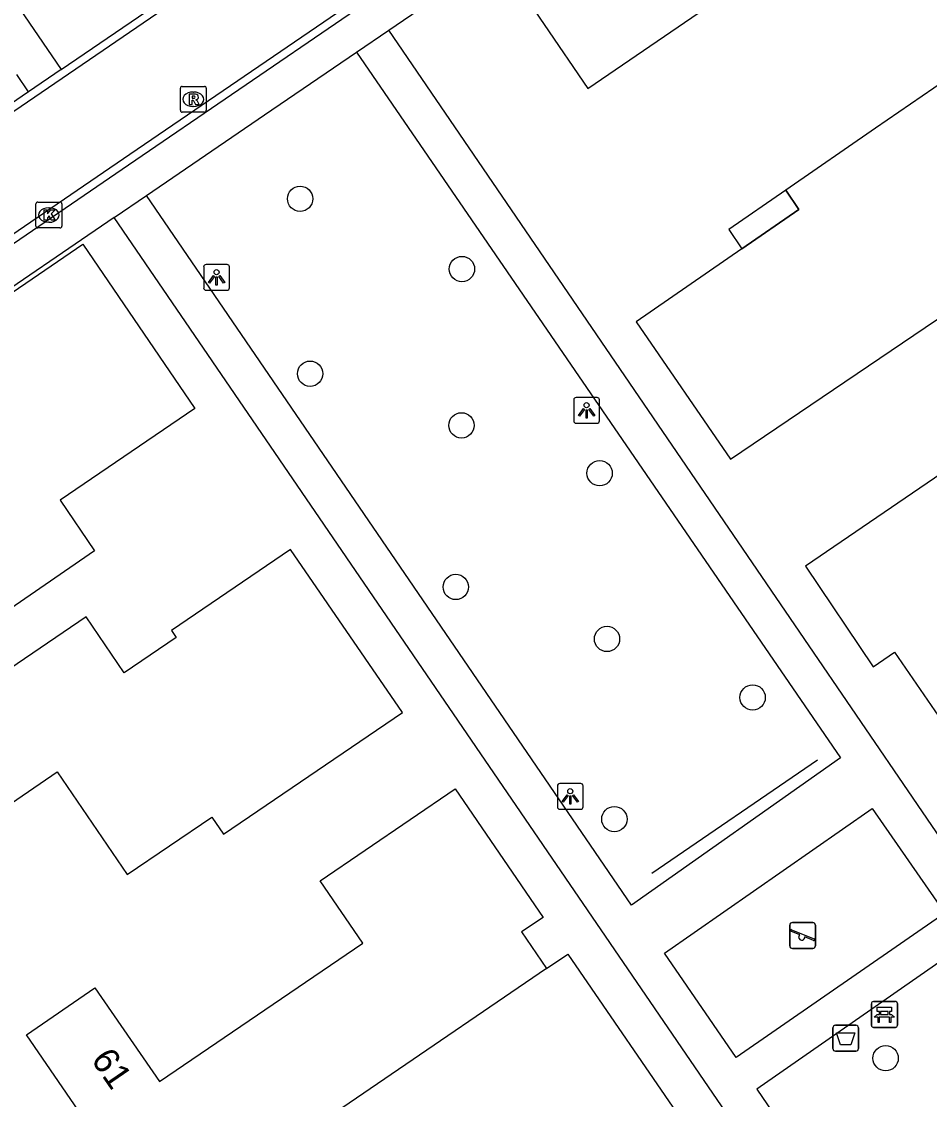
# Model space of a CAD drawing. Extents: x 155275 to 156263, y 382654 to 383635.
# Drawn here: x 155711.19 to 155746.27, y 383313.6 to 383355.27 of the extents above; entities that cross this region are included whole.
import ezdxf

# ---------------------------------------------------------------- set-up
doc = ezdxf.new("R2010")
doc.units = 0
for name, color, linetype in [('IMGEO_Afvalbak', 7, 'Continuous'), ('IMGEO_Bank', 7, 'Continuous'), ('IMGEO_Boom', 7, 'Continuous'), ('IMGEO_Hek', 7, 'Continuous'), ('IMGEO_Kolk', 7, 'Continuous'), ('IMGEO_Lichtpunt', 7, 'Continuous'), ('IMGEO_Pand', 7, 'Continuous'), ('IMGEO_Pand_nummerreeks', 7, 'Continuous'), ('IMGEO_Pand_overbouw', 7, 'Continuous'), ('IMGEO_Rijbaan_lokaal_gesloten', 7, 'Continuous'), ('IMGEO_Rioolput', 7, 'Continuous'), ('IMGEO_Speelvoorziening', 7, 'Continuous'), ('IMGEO_Voetpad_open', 7, 'Continuous')]:
    doc.layers.add(name, color=color, linetype=linetype)

msp = doc.modelspace()

# ---------------------------------------------------------------- linework, layer by layer
at = {"layer": 'IMGEO_Afvalbak'}
for p, q in [((155742.535, 383315.568), (155742.535, 383316.368)), ((155742.535, 383316.368), (155742.535, 383315.568)), ((155742.635, 383316.468), (155743.425, 383316.468)), ((155743.425, 383316.468), (155742.635, 383316.468)), ((155743.525, 383316.368), (155743.525, 383315.568)), ((155743.525, 383315.568), (155743.525, 383316.368)), ((155743.425, 383315.468), (155742.635, 383315.468)), ((155742.635, 383315.468), (155743.425, 383315.468))]:
    msp.add_line(p, q, dxfattribs=at)
msp.add_lwpolyline([(155742.678, 383316.182), (155743.382, 383316.182), (155743.233, 383315.712), (155742.827, 383315.712), (155742.678, 383316.182)], dxfattribs=at)
for centre, start, end in [((155742.635, 383316.368), 90, 180), ((155742.635, 383316.368), 90, 180), ((155743.425, 383316.368), 0, 90), ((155743.425, 383316.368), 360, 90), ((155742.635, 383315.568), 180, 270), ((155742.635, 383315.568), 180, 270), ((155743.425, 383315.568), 270, 0), ((155743.425, 383315.568), 270, 0)]:
    msp.add_arc(centre, 0.1, start, end, dxfattribs=at)
at = {"layer": 'IMGEO_Bank'}
for p, q in [((155744.028, 383316.463), (155744.028, 383317.304)), ((155744.028, 383317.304), (155744.028, 383316.463)), ((155744.103, 383317.388), (155744.944, 383317.388)), ((155744.944, 383317.388), (155744.103, 383317.388)), ((155744.337, 383316.894), (155744.337, 383317)), ((155744.381, 383317), (155744.381, 383316.894)), ((155744.669, 383317.006), (155744.387, 383317.006)), ((155744.675, 383316.894), (155744.675, 383317)), ((155744.719, 383317), (155744.719, 383316.894)), ((155745.028, 383317.313), (155745.028, 383316.472)), ((155745.028, 383316.472), (155745.028, 383317.313)), ((155744.725, 383316.786), (155744.332, 383316.786)), ((155744.387, 383316.888), (155744.669, 383316.888)), ((155744.953, 383316.388), (155744.112, 383316.388)), ((155744.112, 383316.388), (155744.953, 383316.388))]:
    msp.add_line(p, q, dxfattribs=at)
for points in [[(155744.331, 383317.006), (155744.245, 383317.006), (155744.245, 383317.167), (155744.808, 383317.167), (155744.808, 383317.006), (155744.725, 383317.006)], [(155744.275, 383316.786), (155744.133, 383316.786), (155744.245, 383316.888), (155744.331, 383316.888)], [(155744.325, 383316.779), (155744.325, 383316.572), (155744.282, 383316.572), (155744.282, 383316.779)], [(155744.725, 383316.888), (155744.808, 383316.888), (155744.92, 383316.786), (155744.781, 383316.786)], [(155744.775, 383316.779), (155744.775, 383316.572), (155744.731, 383316.572), (155744.731, 383316.779)]]:
    msp.add_lwpolyline(points, dxfattribs=at)
for centre, radius, start, end in [((155744.106, 383317.31), 0.0779, 92.4484, 184.2845), ((155744.106, 383317.31), 0.0779, 92.4484, 184.2845), ((155744.33, 383316.999), 0.00671, 2.8957, 87.1043), ((155744.387, 383316.999), 0.00671, 92.8957, 177.1043), ((155744.669, 383316.999), 0.00671, 2.8957, 87.1043), ((155744.726, 383316.999), 0.00671, 92.8957, 177.1043), ((155744.95, 383317.31), 0.0779, 2.4484, 94.2845), ((155744.95, 383317.31), 0.0779, 2.4484, 94.2845), ((155744.275, 383316.779), 0.00671, 2.8957, 87.1043), ((155744.332, 383316.779), 0.00671, 92.8957, 177.1043), ((155744.33, 383316.895), 0.00671, 272.8957, 357.1043), ((155744.387, 383316.895), 0.00671, 182.8957, 267.1043), ((155744.669, 383316.895), 0.00671, 272.8957, 357.1043), ((155744.726, 383316.895), 0.00671, 182.8957, 267.1043), ((155744.724, 383316.779), 0.00671, 2.8957, 87.1043), ((155744.781, 383316.779), 0.00671, 92.8957, 177.1043), ((155744.106, 383316.466), 0.0779, 182.4484, 274.2845), ((155744.106, 383316.466), 0.0779, 182.4484, 274.2845), ((155744.95, 383316.466), 0.0779, 272.4484, 4.2845), ((155744.95, 383316.466), 0.0779, 272.4484, 4.2845)]:
    msp.add_arc(centre, radius, start, end, dxfattribs=at)
at = {"layer": 'IMGEO_Boom'}
for centre in [(155721.954, 383348.418), (155728.207, 383345.703), (155722.34, 383341.656), (155728.188, 383339.659), (155733.527, 383337.809), (155727.968, 383333.413), (155733.811, 383331.402), (155739.437, 383329.141), (155734.096, 383324.438), (155744.576, 383315.195)]:
    msp.add_circle(centre, 0.489, dxfattribs=at)
at = {"layer": 'IMGEO_Hek'}
msp.add_lwpolyline([(155735.54, 383322.354), (155741.949, 383326.733)], dxfattribs=at)
at = {"layer": 'IMGEO_Kolk'}
for p, q in [((155711.824, 383348.291), (155712.676, 383348.291)), ((155711.749, 383347.365), (155711.749, 383348.217)), ((155712.237, 383348.071), (155712.262, 383348.071)), ((155712.75, 383348.217), (155712.75, 383347.365)), ((155712.26, 383347.511), (155712.235, 383347.511)), ((155712.676, 383347.291), (155711.824, 383347.291))]:
    msp.add_line(p, q, dxfattribs=at)
for points in [[(155711.824, 383348.291), (155712.676, 383348.291)], [(155711.749, 383347.365), (155711.749, 383348.217)], [(155712.07, 383347.991), (155712.193, 383347.991), (155712.193, 383347.84), (155712.323, 383347.991), (155712.487, 383347.991), (155712.341, 383347.84), (155712.494, 383347.591), (155712.342, 383347.591), (155712.257, 383347.755), (155712.193, 383347.688), (155712.193, 383347.591), (155712.07, 383347.591), (155712.07, 383347.991)], [(155712.75, 383348.217), (155712.75, 383347.365)], [(155712.676, 383347.291), (155711.824, 383347.291)]]:
    msp.add_lwpolyline(points, dxfattribs=at)
for centre, start, end in [((155711.826, 383348.215), 91.552, 178.448), ((155711.826, 383348.215), 91.552, 178.448), ((155712.674, 383348.215), 1.552, 88.448), ((155712.674, 383348.215), 1.552, 88.448), ((155711.826, 383347.367), 181.552, 268.448), ((155711.826, 383347.367), 181.552, 268.448), ((155712.674, 383347.367), 271.552, 358.448), ((155712.674, 383347.367), 271.552, 358.448)]:
    msp.add_arc(centre, 0.0765, start, end, dxfattribs=at)
for centre, major_axis, ratio, start_param, end_param in [((155712.236, 383347.791), (-0.387, 0.002), 0.722429, 4.712389, 7.853982), ((155712.261, 383347.791), (-0.39, 0.002), 0.717154, 1.570796, 4.712389)]:
    msp.add_ellipse(centre, major_axis=major_axis, ratio=ratio, start_param=start_param, end_param=end_param, dxfattribs=at)
at = {"layer": 'IMGEO_Lichtpunt'}
for p, q in [((155718.229, 383345.783), (155718.229, 383344.976)), ((155718.229, 383345.783), (155718.229, 383344.976)), ((155719.131, 383345.878), (155718.323, 383345.878)), ((155719.131, 383345.878), (155718.323, 383345.878)), ((155719.225, 383344.976), (155719.225, 383345.783)), ((155719.225, 383344.976), (155719.225, 383345.783)), ((155718.323, 383344.882), (155719.131, 383344.882)), ((155718.323, 383344.882), (155719.131, 383344.882)), ((155732.524, 383340.642), (155732.524, 383339.835)), ((155732.524, 383340.642), (155732.524, 383339.835)), ((155733.426, 383340.737), (155732.618, 383340.737)), ((155733.426, 383340.737), (155732.618, 383340.737)), ((155733.52, 383339.835), (155733.52, 383340.642)), ((155733.52, 383339.835), (155733.52, 383340.642)), ((155732.618, 383339.741), (155733.426, 383339.741)), ((155732.618, 383339.741), (155733.426, 383339.741)), ((155732.795, 383325.814), (155731.987, 383325.814)), ((155732.795, 383325.814), (155731.987, 383325.814)), ((155731.893, 383325.719), (155731.893, 383324.912)), ((155731.893, 383325.719), (155731.893, 383324.912)), ((155732.889, 383324.912), (155732.889, 383325.719)), ((155732.889, 383324.912), (155732.889, 383325.719)), ((155731.987, 383324.818), (155732.795, 383324.818)), ((155731.987, 383324.818), (155732.795, 383324.818))]:
    msp.add_line(p, q, dxfattribs=at)
for points in [[(155718.603, 383345.447), (155718.642, 383345.419), (155718.454, 383345.157), (155718.416, 383345.184), (155718.603, 383345.447)], [(155718.705, 383345.399), (155718.752, 383345.399), (155718.752, 383345.077), (155718.705, 383345.077), (155718.705, 383345.399)], [(155718.815, 383345.419), (155718.853, 383345.446), (155719.04, 383345.184), (155719.001, 383345.156), (155718.815, 383345.419)], [(155732.898, 383340.306), (155732.937, 383340.278), (155732.749, 383340.016), (155732.711, 383340.043), (155732.898, 383340.306)], [(155733, 383340.258), (155733.047, 383340.258), (155733.047, 383339.936), (155733, 383339.936), (155733, 383340.258)], [(155733.11, 383340.278), (155733.148, 383340.305), (155733.335, 383340.043), (155733.296, 383340.015), (155733.11, 383340.278)], [(155732.267, 383325.383), (155732.306, 383325.355), (155732.118, 383325.093), (155732.08, 383325.12), (155732.267, 383325.383)], [(155732.369, 383325.335), (155732.416, 383325.335), (155732.416, 383325.013), (155732.369, 383325.013), (155732.369, 383325.335)], [(155732.479, 383325.355), (155732.517, 383325.382), (155732.704, 383325.12), (155732.665, 383325.092), (155732.479, 383325.355)]]:
    msp.add_lwpolyline(points, dxfattribs=at)
for centre in [(155718.728, 383345.581), (155733.023, 383340.44), (155732.392, 383325.517)]:
    msp.add_circle(centre, 0.0994, dxfattribs=at)
for centre, start, end in [((155718.323, 383345.783), 90, 180), ((155718.323, 383345.783), 90, 180), ((155719.131, 383345.783), 0, 90), ((155719.131, 383345.783), 0, 90), ((155718.323, 383344.976), 180, 270), ((155718.323, 383344.976), 180, 270), ((155719.131, 383344.976), 270, 0), ((155719.131, 383344.976), 270, 360), ((155732.618, 383340.642), 90, 180), ((155732.618, 383340.642), 90, 180), ((155733.426, 383340.642), 0, 90), ((155733.426, 383340.642), 0, 90), ((155732.618, 383339.835), 180, 270), ((155732.618, 383339.835), 180, 270), ((155733.426, 383339.835), 270, 0), ((155733.426, 383339.835), 270, 360), ((155731.987, 383325.719), 90, 180), ((155731.987, 383325.719), 90, 180), ((155732.795, 383325.719), 0, 90), ((155732.795, 383325.719), 0, 90), ((155731.987, 383324.912), 180, 270), ((155731.987, 383324.912), 180, 270), ((155732.795, 383324.912), 270, 0), ((155732.795, 383324.912), 270, 360)]:
    msp.add_arc(centre, 0.0946, start, end, dxfattribs=at)
at = {"layer": 'IMGEO_Pand'}
for points in [[(155745.43, 383361.131), (155742.039, 383366.086), (155729.692, 383357.646), (155733.064, 383352.687), (155742.448, 383359.095)], [(155734.932, 383343.667), (155738.587, 383338.351), (155747.887, 383344.659), (155746.82, 383346.257), (155749.459, 383348.086), (155753.145, 383350.641), (155750.037, 383355.171), (155744.186, 383351.143), (155740.721, 383348.752), (155741.22, 383348.005), (155739.017, 383346.48), (155734.932, 383343.667)], [(155712.69, 383336.769), (155714.016, 383334.808), (155709.604, 383331.778), (155703.922, 383340.076), (155713.558, 383346.665), (155717.883, 383340.315), (155712.69, 383336.769)], [(155757.25, 383336.754), (155756.222, 383338.246), (155752.849, 383335.923), (155750.035, 383340.052), (155741.483, 383334.214), (155744.094, 383330.327), (155744.921, 383330.894), (155748.035, 383326.353), (155748.208, 383326.472)], [(155725.912, 383328.554), (155721.583, 383334.859), (155716.984, 383331.725), (155717.164, 383331.46), (155715.163, 383330.089), (155713.691, 383332.255), (155705.396, 383326.616), (155703.742, 383325.492), (155705.288, 383323.217), (155706.97, 383324.31), (155707.84, 383323.036), (155712.565, 383326.27), (155715.271, 383322.292), (155718.544, 383324.516), (155718.994, 383323.854), (155725.912, 383328.554)], [(155718.414, 383309.742), (155717.048, 383311.729), (155715.234, 383310.476), (155711.378, 383316.095), (155714.029, 383317.915), (155716.516, 383314.29), (155724.373, 383319.645), (155722.728, 383322.057), (155727.941, 383325.612), (155731.339, 383320.63), (155730.513, 383320.077), (155731.476, 383318.658)], [(155731.476, 383318.658), (155732.298, 383319.22), (155736.952, 383312.438), (155732.083, 383309.164), (155730.299, 383311.75), (155722.139, 383306.171)], [(155731.476, 383318.658), (155718.414, 383309.742)]]:
    msp.add_lwpolyline(points, dxfattribs=at)
at = {"layer": 'IMGEO_Pand_overbouw'}
msp.add_lwpolyline([(155740.721, 383348.752), (155738.519, 383347.232), (155739.017, 383346.48), (155741.22, 383348.005)], close=True, dxfattribs=at)
at = {"layer": 'IMGEO_Rijbaan_lokaal_gesloten'}
for points in [[(155779.897, 383398.895), (155721.169, 383358.828), (155661.404, 383317.986), (155661.244, 383318.235)], [(155782.106, 383395.69), (155715.377, 383350.126), (155663.845, 383314.887), (155664.009, 383314.637)], [(155693.872, 383335.059), (155715.33, 383349.733), (155745.158, 383370.123)], [(155712.721, 383353.417), (155720.795, 383358.936)], [(155712.721, 383353.417), (155711.461, 383352.556)], [(155711.461, 383352.556), (155708.502, 383350.534)]]:
    msp.add_lwpolyline(points, dxfattribs=at)
at = {"layer": 'IMGEO_Rioolput'}
for p, q in [((155717.329, 383351.838), (155717.329, 383352.69)), ((155717.404, 383352.764), (155718.256, 383352.764)), ((155717.817, 383352.544), (155717.842, 383352.544)), ((155718.33, 383352.69), (155718.33, 383351.838)), ((155718.256, 383351.764), (155717.404, 383351.764)), ((155717.84, 383351.984), (155717.815, 383351.984))]:
    msp.add_line(p, q, dxfattribs=at)
for points in [[(155717.329, 383351.838), (155717.329, 383352.69)], [(155717.404, 383352.764), (155718.256, 383352.764)], [(155717.918, 383352.462), (155717.666, 383352.464), (155717.666, 383352.064)], [(155718.33, 383352.69), (155718.33, 383351.838)], [(155717.666, 383352.064), (155717.79, 383352.064), (155717.79, 383352.226), (155717.801, 383352.226)], [(155717.844, 383352.383), (155717.79, 383352.383), (155717.79, 383352.302)], [(155717.79, 383352.302), (155717.842, 383352.302)], [(155717.848, 383352.197), (155717.919, 383352.064), (155718.059, 383352.064), (155717.994, 383352.19)], [(155718.256, 383351.764), (155717.404, 383351.764)]]:
    msp.add_lwpolyline(points, dxfattribs=at)
for centre, radius, start, end in [((155717.406, 383352.688), 0.0765, 91.552, 178.448), ((155717.406, 383352.688), 0.0765, 91.552, 178.448), ((155717.917, 383352.352), 0.109, 350.3612, 89.416), ((155718.254, 383352.688), 0.0765, 1.552, 88.448), ((155718.254, 383352.688), 0.0765, 1.552, 88.448), ((155717.8, 383352.173), 0.0533, 26.0293, 88.6989), ((155717.826, 383352.491), 0.19, 274.7715, 282.9687), ((155717.85, 383352.287), 0.0964, 77.0061, 93.1865), ((155717.864, 383352.344), 0.0378, 276.6634, 79.6772), ((155717.915, 383352.352), 0.112, 277.5842, 350.9817), ((155717.899, 383352.137), 0.108, 29.5134, 73.7905), ((155717.406, 383351.84), 0.0765, 181.552, 268.448), ((155717.406, 383351.84), 0.0765, 181.552, 268.448), ((155718.254, 383351.84), 0.0765, 271.552, 358.448), ((155718.254, 383351.84), 0.0765, 271.552, 358.448)]:
    msp.add_arc(centre, radius, start, end, dxfattribs=at)
for centre, major_axis, ratio, start_param, end_param in [((155717.816, 383352.264), (-0.387, 0.002), 0.722429, 4.712389, 7.853982), ((155717.841, 383352.264), (-0.39, 0.002), 0.717154, 1.570796, 4.712389)]:
    msp.add_ellipse(centre, major_axis=major_axis, ratio=ratio, start_param=start_param, end_param=end_param, dxfattribs=at)
at = {"layer": 'IMGEO_Speelvoorziening'}
for p, q in [((155740.872, 383319.54), (155740.872, 383320.34)), ((155740.872, 383320.34), (155740.872, 383319.54)), ((155740.972, 383320.44), (155741.762, 383320.44)), ((155741.762, 383320.44), (155740.972, 383320.44)), ((155741.862, 383320.34), (155741.862, 383319.54)), ((155741.862, 383319.54), (155741.862, 383320.34)), ((155741.255, 383319.968), (155740.916, 383320.105)), ((155740.941, 383320.165), (155741.817, 383319.812)), ((155741.793, 383319.752), (155741.453, 383319.889)), ((155741.762, 383319.44), (155740.972, 383319.44)), ((155740.972, 383319.44), (155741.762, 383319.44))]:
    msp.add_line(p, q, dxfattribs=at)
for centre, radius, start, end in [((155740.972, 383320.34), 0.1, 90, 180), ((155740.972, 383320.34), 0.1, 90, 180), ((155741.762, 383320.34), 0.1, 0, 90), ((155741.762, 383320.34), 0.1, 360, 90), ((155740.929, 383320.135), 0.0327, 68.078, 248.078), ((155741.334, 383319.878), 0.12, 130.9928, 5.1632), ((155740.972, 383319.54), 0.1, 180, 270), ((155740.972, 383319.54), 0.1, 180, 270), ((155741.762, 383319.54), 0.1, 270, 0), ((155741.762, 383319.54), 0.1, 270, 0), ((155741.805, 383319.782), 0.0327, 248.078, 68.078)]:
    msp.add_arc(centre, radius, start, end, dxfattribs=at)
at = {"layer": 'IMGEO_Voetpad_open'}
for points in [[(155725.382, 383354.939), (155745.715, 383368.811)], [(155720.795, 383358.936), (155717.961, 383363.071), (155709.882, 383357.573), (155712.721, 383353.417)], [(155724.137, 383354.089), (155725.382, 383354.939)], [(155764.327, 383297.885), (155763.878, 383298.522), (155725.382, 383354.939)], [(155716.015, 383348.542), (155720.581, 383351.663), (155724.137, 383354.089)], [(155724.137, 383354.089), (155742.832, 383326.803), (155734.762, 383321.106), (155716.015, 383348.542)], [(155711.461, 383352.556), (155711.009, 383353.222)], [(155714.768, 383347.689), (155716.015, 383348.542)], [(155714.768, 383347.689), (155698.263, 383336.406), (155694.36, 383333.757)], [(155756.341, 383286.918), (155755.683, 383287.816), (155714.768, 383347.689)], [(155744.055, 383324.846), (155746.857, 383320.807), (155738.798, 383315.226), (155736.031, 383319.256), (155744.055, 383324.846)], [(155763.51, 383296.526), (155763.357, 383296.696), (155747.691, 383319.636), (155739.6, 383314.001), (155757.081, 383288.349), (155757.279, 383288.068)]]:
    msp.add_lwpolyline(points, dxfattribs=at)

# ---------------------------------------------------------------- texts
at = {"layer": 'IMGEO_Pand_nummerreeks'}
msp.add_text('61', height=1, rotation=304.4575, dxfattribs=at).set_placement((155713.852, 383315.141))

doc.saveas('drawing.dxf')
